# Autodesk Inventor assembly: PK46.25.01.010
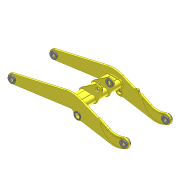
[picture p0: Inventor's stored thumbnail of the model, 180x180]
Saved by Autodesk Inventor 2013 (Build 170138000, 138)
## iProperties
Created: 2005-04
Part Number: PK46.25.01.010
Document SubType Name: Assembly
Designer: salex
Manufacturer: Standard
Standards Organization: Custom
Author: salex
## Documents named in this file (9)
- C:\Product Design Suite 2013 Test Drive\Inventor to Showcase\Workspace\Assy, Chassis, Front\PK46.25.01.010.iam
- C:\Product Design Suite 2013 Test Drive\Inventor to Showcase\Workspace\Assy, Chassis, Front\PK46.25.01.001.ipt
- C:\Product Design Suite 2013 Test Drive\Inventor to Showcase\Workspace\Assy, Chassis, Front\PK46.25.01.002.ipt
- C:\Product Design Suite 2013 Test Drive\Inventor to Showcase\Workspace\Assy, Chassis, Front\PK46.25.01.003.ipt
- C:\Product Design Suite 2013 Test Drive\Inventor to Showcase\Workspace\Assy, Chassis, Front\PK46.25.01.004.ipt
- C:\Product Design Suite 2013 Test Drive\Inventor to Showcase\Workspace\Assy, Chassis, Front\PK46.25.01.008.ipt
- C:\Product Design Suite 2013 Test Drive\Inventor to Showcase\Workspace\Assy, Chassis, Front\PK46.25.01.012.ipt
- C:\Product Design Suite 2013 Test Drive\Inventor to Showcase\Workspace\Assy, Chassis, Front\PK46.25.01.020.iam
- PK46.25.01.020.iam
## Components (19 placed, 7 different names)
1. PK46.25.01.001:1 — Insert:3, Insert:4, Insert:7, Insert:8, Mate:1, Mate:2, Mate:3, Insert:10, Insert:11, Angle:1
2. PK46.25.01.002:1 — Insert:1, Insert:2, Insert:5, Insert:6, Mate:1, Mate:2, Mate:3, Insert:9, Insert:12, Angle:2, Mate:9, Mate:10
3. PK46.25.01.003:1 — Insert:3, Insert:14
4. PK46.25.01.003:2 — Insert:4, Insert:16
5. PK46.25.01.003:3 — Insert:1, Insert:13
6. PK46.25.01.003:4 — Insert:2, Insert:15
7. PK46.25.01.003:5 — Insert:5
8. PK46.25.01.003:6 — Insert:6
9. PK46.25.01.003:7 — Insert:7
10. PK46.25.01.003:8 — Insert:8
11. PK46.25.01.004:1 — Insert:10
12. PK46.25.01.004:2 — Insert:9
13. PK46.25.01.008:1 — Insert:11, Mate:6, Mate:7, Mate:8
14. PK46.25.01.008:2 — Insert:12, Mate:4, Mate:5
15. PK46.25.01.012:1 — Insert:15
16. PK46.25.01.012:2 — Insert:16, Angle:1
17. PK46.25.01.012:3 — Insert:13, Angle:2
18. PK46.25.01.012:4 — Insert:14
19. PK46.25.01.020:1 [sub-assembly] — Mate:4, Mate:5, Mate:6, Mate:7, Mate:8, Mate:14, Flush:1, Flush:5, Angle:4, Mate:20, Mate:21
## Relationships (34: Insert 16, Mate 13, Angle 3, Flush 2)
- Insert:1: PK46.25.01.002:1 ↔ PK46.25.01.003:3
- Insert:2: PK46.25.01.002:1 ↔ PK46.25.01.003:4
- Insert:3: PK46.25.01.001:1 ↔ PK46.25.01.003:1
- Insert:4: PK46.25.01.001:1 ↔ PK46.25.01.003:2
- Insert:5: PK46.25.01.002:1 ↔ PK46.25.01.003:5
- Insert:6: PK46.25.01.002:1 ↔ PK46.25.01.003:6
- Insert:7: PK46.25.01.001:1 ↔ PK46.25.01.003:7
- Insert:8: PK46.25.01.001:1 ↔ PK46.25.01.003:8
- Mate:1: PK46.25.01.001:1 ↔ PK46.25.01.002:1
- Mate:2: PK46.25.01.001:1 ↔ PK46.25.01.002:1
- Mate:3: PK46.25.01.001:1 ↔ PK46.25.01.002:1
- Insert:9: PK46.25.01.002:1 ↔ PK46.25.01.004:2
- Insert:10: PK46.25.01.001:1 ↔ PK46.25.01.004:1
- Insert:11: PK46.25.01.001:1 ↔ PK46.25.01.008:1
- Insert:12: PK46.25.01.002:1 ↔ PK46.25.01.008:2
- Mate:4: PK46.25.01.008:2 ↔ PK46.25.01.020:1
- Mate:5: PK46.25.01.008:2 ↔ PK46.25.01.020:1
- Mate:6: PK46.25.01.008:1 ↔ PK46.25.01.020:1
- Mate:7: PK46.25.01.008:1 ↔ PK46.25.01.020:1
- Mate:8: PK46.25.01.008:1 ↔ PK46.25.01.020:1
- Insert:13: PK46.25.01.003:3 ↔ PK46.25.01.012:3
- Insert:14: PK46.25.01.003:1 ↔ PK46.25.01.012:4
- Insert:15: PK46.25.01.003:4 ↔ PK46.25.01.012:1
- Insert:16: PK46.25.01.003:2 ↔ PK46.25.01.012:2
- Angle:1: PK46.25.01.001:1 ↔ PK46.25.01.012:2
- Angle:2: PK46.25.01.002:1 ↔ PK46.25.01.012:3
- Mate:9: PK46.25.01.002:1
- Mate:10: PK46.25.01.002:1
- Mate:14: PK46.25.01.020:1
- Flush:1: PK46.25.01.020:1
- Flush:5: PK46.25.01.020:1
- Angle:4: PK46.25.01.020:1
- Mate:20: PK46.25.01.020:1
- Mate:21: PK46.25.01.020:1
